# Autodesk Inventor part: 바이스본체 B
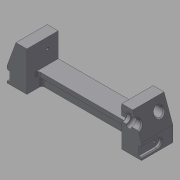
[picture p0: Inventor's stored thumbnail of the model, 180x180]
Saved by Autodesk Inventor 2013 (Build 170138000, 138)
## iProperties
Created: 2017-04
Part Number: 바이스본체 B
Material: 알루미늄 6061
Document SubType Name: Modeling
Designer: mduedu
Density: 1 g/cm^3
Author: mduedu
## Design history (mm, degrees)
sketch "스케치1"
  geometry: L1 (-75, 0)-(75, 0); L2 (-75, 0)-(-75, 17); L3 (-53, 17)-(53, 17); L4 (75, 17)-(75, 0); L5 (-75, 17)-(-65.173, 44); L6 (-65.173, 44)-(-53, 44); L7 (-53, 44)-(-53, 17); L8 (0, 0)-(0, 17); L9 (75, 17)-(65.173, 44); L10 (65.173, 44)-(53, 44); L11 (53, 44)-(53, 17); 1 further point
  constraints: 22 end point, 4 perpendicular, 2 horizontal alignment, 2 midpoint, 2 symmetric about line, 1 coincident, 1 collinear, 1 horizontal, 1 vertical
  dimensions: "d0" = 150 distance of L1.start L1.end; "d1" = 17 distance of L1.start L2.end; "d2" = 27 distance of L3.start L6.end; "d3" = 22 distance of L3.start L2.end; "d4" = 70 deg angle of L3 L5; "d54" = 20 deg angle of L9 L4
extrude "돌출1" new body sketch "스케치1" stored distance "d5" = 70; taper "d6" = 0 deg
sketch "스케치2"
  geometry: L1 (0, 70)-(106, 70) reference; L2 (106, 70)-(106, 0) reference; L3 (106, 0)-(0, 0) reference; L4 (0, 47)-(106, 47); L5 (106, 47)-(106, 23); L6 (106, 23)-(0, 23); L7 (0, 23)-(0, 47); L8 (0, 70)-(0, 0) reference; 2 further points
  constraints: 8 end point, 2 parallel, 2 point on line, 1 horizontal, 1 horizontal alignment, 1 midpoint, 1 perpendicular
  dimensions: "d7" = 24 distance between parallel lines of L6 L4
extrude "돌출2" cut sketch "스케치2" stored distance "d9" = 70; taper "d10" = 0 deg
sketch "스케치3"
  geometry: L1 (22, -23)-(128, -23) reference; L2 (128, -47)-(22, -47) reference; L3 (22, -18)-(128, -18); L4 (128, -52)-(22, -52); L5 (22, -18)-(22, -52); L6 (128, -18)-(128, -52); 1 further point
  constraints: 8 end point, 3 parallel, 2 point on line, 1 perpendicular
  dimensions: "d11" = 5 distance between parallel lines of L3 L1; "d12" = 5 distance between parallel lines of L4 L2
extrude "돌출3" cut sketch "스케치3" distance "d13" = 12; taper "d14" = 0 deg
fillet "모깎기1" dims "d15" = 3, "d16" = 3
sketch "스케치4"
  geometry: L1 (103, 23)-(3, 23) reference; L2 (0, 26)-(0, 0) reference; L3 (106, 0)-(0, 0) reference; L4 (106, 26)-(106, 0) reference; L5 (96, 0)-(90, 0); L6 (90, 0)-(90, 19.5); L7 (96, 19.5)-(96, 0); L8 (90, 19.5)-(96, 19.5); A1 r 3 centre (3, 26) between (0, 26) and (3, 23) reference; A2 r 3 centre (103, 26) between (103, 23) and (106, 26) reference; 1 further point
  constraints: 8 end point, 2 perpendicular, 1 horizontal, 1 parallel, 1 point on line
  dimensions: "d17" = 10 distance between parallel lines of L7 L4; "d18" = 6 distance between parallel lines of L7 L6; "d27" = 3.5 distance between parallel lines of L8 L1
extrude "돌출4" join sketch "스케치4" distance "d19" = 12; taper "d20" = 0 deg
chamfer "모따기1" distance "d21" = 3; stored, may be unused: second distance "d22" = 2, angle "d23" = 45 deg
chamfer "모따기2" distance "d24" = 3; stored, may be unused: second distance "d25" = 2, angle "d26" = 45 deg
sketch "스케치5"
  geometry: L1 (-15.5, 35.8)-(-15.5, -25.8) reference; L2 (19.5, 0)-(0, 0) reference; C1 r 6.5 at (9.5, 15); 1 further point
  constraints: 1 centre point
  dimensions: "d28" = 13 diameter of C1; "d30" = 15 distance from line of C1.centre L2; "d31" = 25 distance from line of C1.centre L1
extrude "돌출5" cut sketch "스케치5" stored distance "d32" = 12; taper "d33" = 0 deg
sketch "스케치6"
  geometry: C1 r 5 at (-10, 15); C2 r 5 at (-60, 15); A1 r 6.5 centre (-10, 15) between (-15.766, 12) and (-4.234, 12) reference; A2 r 6.5 centre (-60, 15) between (-65.766, 12) and (-54.234, 12) reference; 1 further point
  constraints: 2 centre point, 2 coincident
  dimensions: "d34" = 10 diameter of C1; "d35" = 10 diameter of C2 (= d34)
extrude "돌출6" cut sketch "스케치6" stored distance "d36" = 12; taper "d37" = 0 deg
chamfer "모따기3" distance "d38" = 1; stored, may be unused: second distance "d39" = 2, angle "d40" = 45 deg
chamfer "모따기4" distance "d41" = 1; stored, may be unused: second distance "d42" = 2, angle "d43" = 45 deg
sketch "스케치7"
  geometry: L1 (-35, 35.8)-(-35, -25.8) reference; L2 (-70, 0)-(0, 0) reference; C1 r 5 at (-35, 15); 1 further point
  constraints: 1 centre point, 1 point on line
  dimensions: "d44" = 10 diameter of C1; "d45" = 15 distance from line of C1.centre L2
extrude "돌출7" cut sketch "스케치7" stored distance "d46" = 12; taper "d47" = 0 deg
chamfer "모따기5" distance "d48" = 1; stored, may be unused: second distance "d49" = 2, angle "d50" = 45 deg
node "작업축1"
sketch "스케치8"
  geometry: L1 (-105, 32)-(105, 32) reference; L2 (58, 32)-(64, 32); L3 (64, 32)-(64, 40); L4 (64, 40)-(58, 40); L5 (58, 40)-(58, 32); L6 (53, 38)-(53, 26) reference; 1 further point
  constraints: 8 end point, 2 parallel, 1 horizontal, 1 perpendicular, 1 point on line
  dimensions: "d51" = 5 distance from line of L6 L2.start; "d52" = 6 distance of L3.end L4.end; "d53" = 16 diameter of L4 L1
revolve "회전1" sketch "스케치8" stored, may be unused: angle "d55" = 90 deg
fillet "모깎기2"
chamfer "모따기6" distance "d56" = 1; stored, may be unused: second distance "d57" = 2, angle "d58" = 45 deg
sketch "스케치9"
  geometry: L1 (17.5, 3)-(52.5, 3); L2 (52.5, 13)-(17.5, 13); L3 (70, 0)-(0, 0) reference; L4 (17.5, 8)-(52.5, 8); A1 r 5 centre (17.5, 8) between (17.5, 13) and (17.5, 3); A2 r 5 centre (52.5, 8) between (52.5, 3) and (52.5, 13); 3 further points
  constraints: 6 end point, 4 point on circle, 3 tangent, 2 centre point, 2 midpoint, 2 parallel, 1 horizontal, 1 vertical alignment
  dimensions: "d59" = 35 distance of L4.start L4.end; "d61" = 5 radius of A2; "d62" = 8 distance between parallel lines of L3 L4
extrude "돌출8" cut sketch "스케치9" distance "d63" = 3; taper "d64" = 0 deg
chamfer "모따기7" distance "d65" = 1; stored, may be unused: second distance "d66" = 2, angle "d67" = 45 deg
chamfer "모따기8" distance "d68" = 1; stored, may be unused: second distance "d69" = 2, angle "d70" = 45 deg
feature "분할1"
sketch "스케치10"
  geometry: A1 r 5 centre (0, 0) between (0, 5) and (0, -5) reference; 1 further point
  constraints: 1 coincident
hole "구멍1" sketch "스케치10" at (0, 0) diameter "d71" = 2.459; stored, may be unused: countersink angle "d75" = 90 deg, drill point angle "d77" = 120 deg; dims "d72" = 4.5, "d73" = 4, "d74" = 2, "d76" = 6
sketch "스케치11"
  geometry: L1 (0, 0)-(0, 27) reference; L2 (0, 27)-(-35, 27) reference; 2 further points
  dimensions: "d78" = 12 distance from line of point (-12, 15.5) L1; "d79" = 11.5 distance from line of point (-12, 15.5) L2
hole "구멍2" sketch "스케치11" at (-12, 15.5) diameter "d80" = 3.242; stored, may be unused: countersink angle "d84" = 90 deg, drill point angle "d86" = 120 deg; dims "d81" = 6, "d82" = 4, "d83" = 2, "d85" = 8
node "솔리드1"
mirror "대칭1"
mirror "대칭2"
mirror "대칭3"
mirror "대칭4"
node "투영된 루프1"
